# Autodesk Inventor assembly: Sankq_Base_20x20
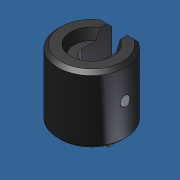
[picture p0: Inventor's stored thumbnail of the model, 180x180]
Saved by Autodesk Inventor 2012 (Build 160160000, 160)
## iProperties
Created: 2013-10
Part Number: Sankq_Base_20x20
Document SubType Name: Assembly
Designer: Admin
Author: Admin
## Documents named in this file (3)
- C:\Andys Backup Data\ANDY'S INVENTOR\INVENTOR LIBRARIES\PARTS LIBRARY\HYDRAULIC VERTICAL ADJUSTMENT\27.9001Telescoping Twin Leg System\SUBCOMPONENTS\Qxx18_crank pump\Sankq_Base_20x20.iam
- C:\Andys Backup Data\ANDY'S INVENTOR\INVENTOR LIBRARIES\PARTS LIBRARY\HYDRAULIC VERTICAL ADJUSTMENT\27.9001Telescoping Twin Leg System\SUBCOMPONENTS\Qxx18_crank pump\NONE.ipt
- C:\Andys Backup Data\ANDY'S INVENTOR\INVENTOR LIBRARIES\PARTS LIBRARY\HYDRAULIC VERTICAL ADJUSTMENT\27.9001Telescoping Twin Leg System\SUBCOMPONENTS\Qxx18_crank pump\NONE_1.ipt
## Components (2 placed, 2 different names)
1. NONE:1
2. NONE_1:1
